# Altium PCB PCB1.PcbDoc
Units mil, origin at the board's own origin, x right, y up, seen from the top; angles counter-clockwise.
Board outline 4740 x 1980 mil, 4 copper layers (Top Layer, GND, Power, Bottom Layer), stack 63.355 mil thick; 55 components, 31 nets, 157 pads, 23 vias.
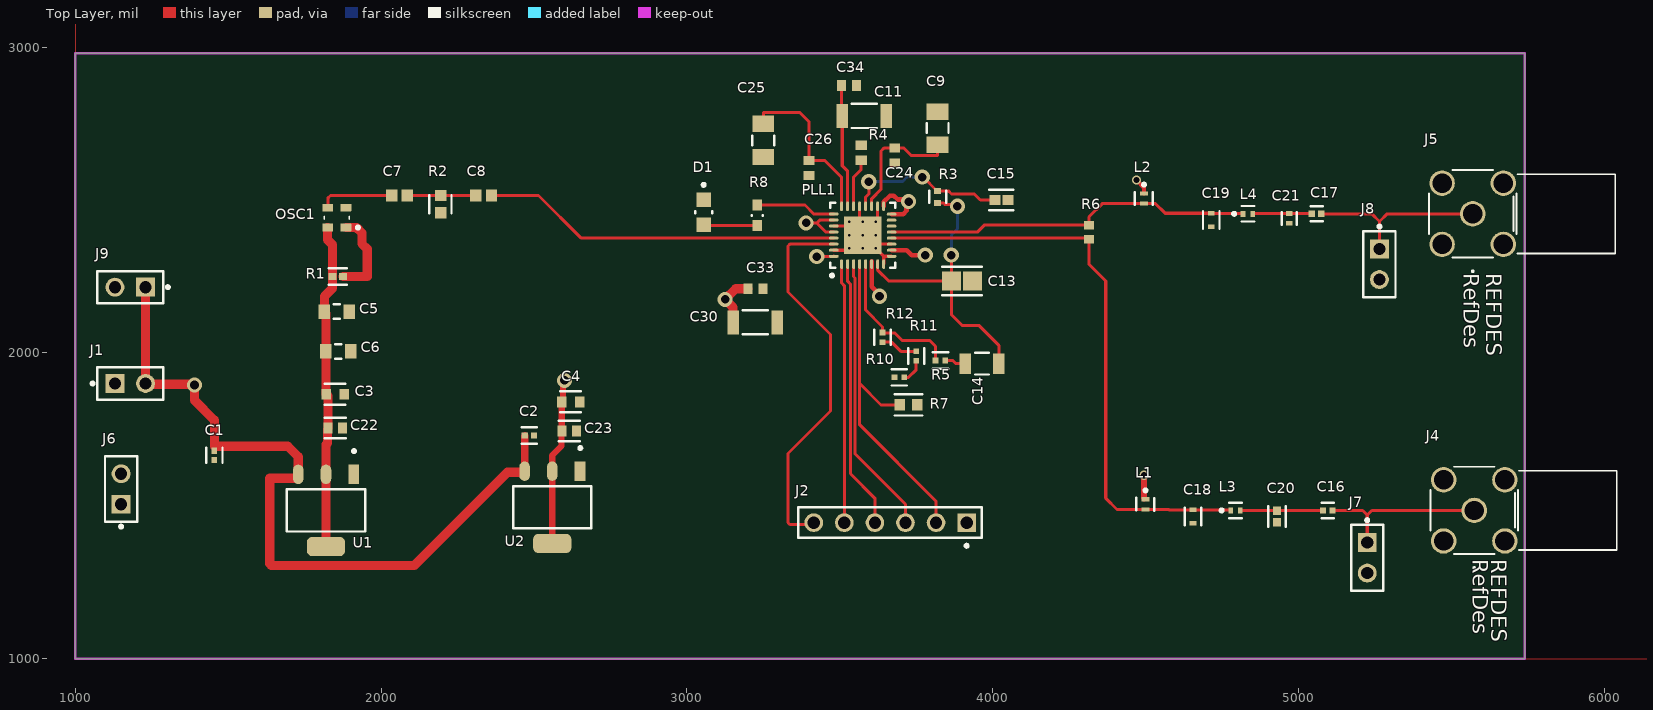
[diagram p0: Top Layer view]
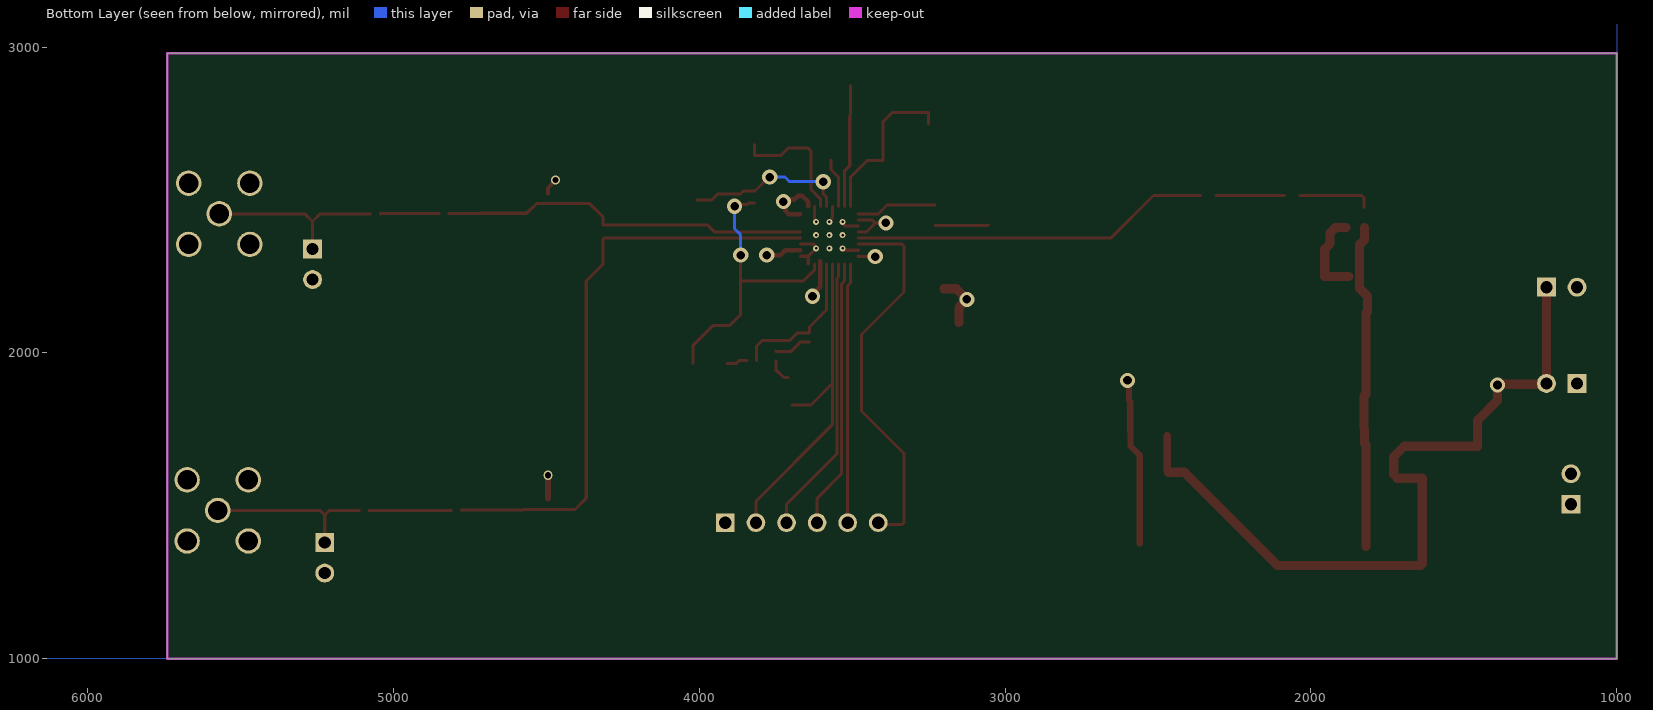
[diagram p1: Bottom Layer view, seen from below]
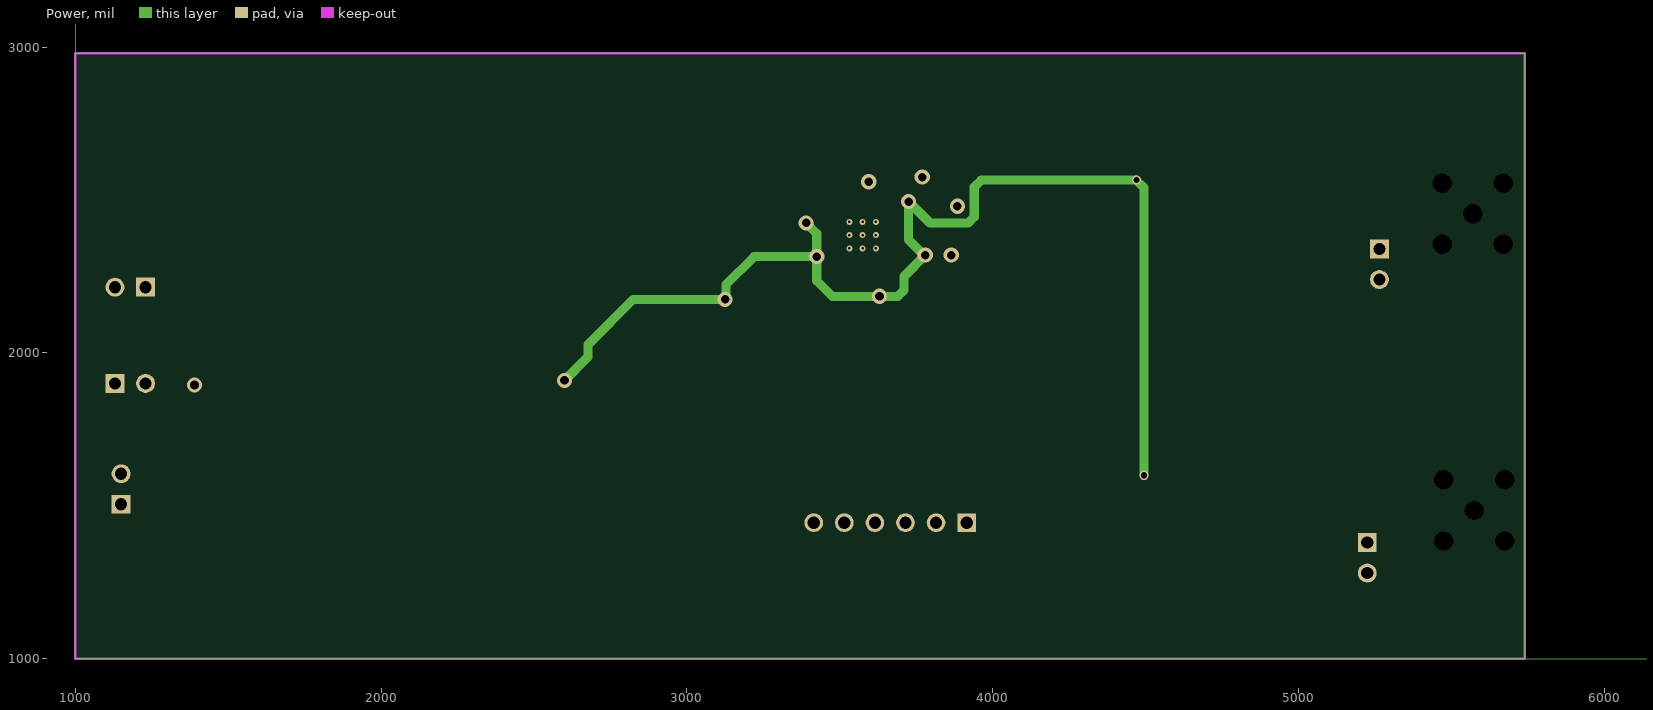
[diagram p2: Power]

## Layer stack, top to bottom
Top Solder: solder mask 1, Solder Resist, Dk 3.6
Top Layer: signal copper 1.378
Dielectric 1: prepreg 7.957, FR-4, Dk 3.61
GND: signal copper 1.378
Core: core 41.929, FR-4, Dk 4.4
Power: signal copper 1.378
Dielectric 2: prepreg 7.957, FR-4, Dk 3.61
Bottom Layer: signal copper 1.378
Bottom Solder: solder mask 1, Solder Resist, Dk 3.6

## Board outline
1000,1000 5740,1000 5740,2980 1000,2980

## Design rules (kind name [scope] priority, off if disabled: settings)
AssemblyTestPointUsage [All] p0: scope1count=1 scope1_0_kind=Board scope1_0_value=Board scope2count=1 scope2_0_kind=Board scope2_0_value=Board commentlength=0
AssemblyTestpoint [All] p0: scope1count=1 scope1_0_kind=Board scope1_0_value=Board scope2count=1 scope2_0_kind=Board scope2_0_value=Board commentlength=0
BoardOutlineClearance [All] p0: scope1count=1 scope1_0_kind=Board scope1_0_value=Board scope2count=1 scope2_0_kind=Board scope2_0_value=Board commentlength=0 gap=15
BoardOutlineClearance [All] p1: gap=15 ignorepadtopadclearanceinfootprint=FALSE
Clearance [All] p0: scope1count=1 scope1_0_kind=Board scope1_0_value=Board scope2count=1 scope2_0_kind=Board scope2_0_value=Board commentlength=0 gap=5
Clearance "Clearance Polygons" [All] p0 off: scope1count=1 scope1_0_kind=Board scope1_0_value=Board scope2count=1 scope2_0_kind=Board scope2_0_value=Board commentlength=48 gap=10 // Protel DXP Scope 1 Expression Was: InPolygon
Clearance "Clearance Polygons" [InPolygon] p1: gap=10 ignorepadtopadclearanceinfootprint=FALSE
Clearance [All] p2: gap=5 ignorepadtopadclearanceinfootprint=FALSE
ComponentClearance [All] p0: scope1count=1 scope1_0_kind=Board scope1_0_value=Board scope2count=1 scope2_0_kind=Board scope2_0_value=Board commentlength=0 gap=1 collisioncheckmode=3
ComponentClearance "HM-TRP & UFL" [All] p0: scope1count=1 scope1_0_kind=Component scope1_0_value=X1 scope2count=1 scope2_0_kind=Component scope2_0_value=U1 commentlength=0 gap=0 collisioncheckmode=3
ComponentClearance "HM-TRP & UFL" [InComponent('X1') vs InComponent('U1')] p1: gap=0 collisioncheckmode=3 verticalgap=0 showdistances=FALSE
ComponentClearance [All] p2: gap=1 collisioncheckmode=3 verticalgap=1 showdistances=FALSE
DiffPairsRouting [All] p0: scope1count=1 scope1_0_kind=Board scope1_0_value=Board scope2count=1 scope2_0_kind=Board scope2_0_value=Board commentlength=0
DiffPairsRouting [All] p1: maxlimit=393.7 minlimit=5 mostfreqgap=8 toplayer_minwidth=5 toplayer_maxwidth=15 toplayer_prefwidth=8 midlayer1_minwidth=5 midlayer1_maxwidth=15 midlayer1_prefwidth=8 midlayer2_minwidth=5 midlayer2_maxwidth=15 midlayer2_prefwidth=8 bottomlayer_minwidth=5 bottomlayer_maxwidth=15 bottomlayer_prefwidth=8 maxuncoupledlength=500
FabricationTestPointUsage [All] p0: scope1count=1 scope1_0_kind=Board scope1_0_value=Board scope2count=1 scope2_0_kind=Board scope2_0_value=Board commentlength=0 valid=0 allowmultiple=FALSE
FabricationTestpoint [All] p0: scope1count=1 scope1_0_kind=Board scope1_0_value=Board scope2count=1 scope2_0_kind=Board scope2_0_value=Board commentlength=0 side=3 testpointundercomponent=TRUE minsize=40 maxsize=100 preferedsize=60 minholesize=0 maxholesize=40 preferedholesize=32 testpointgrid=1
FanoutControl Fanout_Default [All] p0: scope1count=1 scope1_0_kind=Board scope1_0_value=Board scope2count=1 scope2_0_kind=Board scope2_0_value=Board commentlength=30 // Fanout_Default (Default Rule)
FanoutControl Fanout_Small [All] p0 off: scope1count=1 scope1_0_kind=Board scope1_0_value=Board scope2count=1 scope2_0_kind=Board scope2_0_value=Board commentlength=84 // Protel DXP Scope 1 Expression Was: (CompPinCount < 5)   Fanout_Small (Default Rule)
FanoutControl Fanout_SOIC [All] p0 off: scope1count=1 scope1_0_kind=Board scope1_0_value=Board scope2count=1 scope2_0_kind=Board scope2_0_value=Board commentlength=71 // Protel DXP Scope 1 Expression Was: IsSOIC   Fanout_SOIC (Default Rule)
FanoutControl Fanout_LCC [All] p0 off: scope1count=1 scope1_0_kind=Board scope1_0_value=Board scope2count=1 scope2_0_kind=Board scope2_0_value=Board commentlength=69 // Protel DXP Scope 1 Expression Was: IsLCC   Fanout_LCC (Default Rule)
FanoutControl Fanout_BGA [All] p0 off: scope1count=1 scope1_0_kind=Board scope1_0_value=Board scope2count=1 scope2_0_kind=Board scope2_0_value=Board commentlength=69 // Protel DXP Scope 1 Expression Was: IsBGA   Fanout_BGA (Default Rule)
Height [All] p0: scope1count=1 scope1_0_kind=Board scope1_0_value=Board scope2count=1 scope2_0_kind=Board scope2_0_value=Board commentlength=0
HoleSize [All] p0: scope1count=1 scope1_0_kind=Board scope1_0_value=Board scope2count=1 scope2_0_kind=Board scope2_0_value=Board commentlength=0 absolutevalues=TRUE maxlimit=265 minlimit=10 maxpercent=80.000 minpercent=20.000
HoleSize [All] p1: absolutevalues=TRUE maxlimit=265 minlimit=10 maxpercent=80.000 minpercent=20.000
HoleToHoleClearance [All] p0: scope1count=1 scope1_0_kind=Board scope1_0_value=Board scope2count=1 scope2_0_kind=Board scope2_0_value=Board commentlength=0
HoleToHoleClearance [All] p1: gap=10 allowstackedmicrovias=FALSE
LayerPairs [All] p0: scope1count=1 scope1_0_kind=Board scope1_0_value=Board scope2count=1 scope2_0_kind=Board scope2_0_value=Board commentlength=0 enforce=TRUE
MinimumAnnularRing [All] p0: scope1count=1 scope1_0_kind=Board scope1_0_value=Board scope2count=1 scope2_0_kind=Board scope2_0_value=Board commentlength=0 minimumring=4
MinimumAnnularRing [All] p1: minimumring=4
MinimumSolderMaskSliver [All] p0: scope1count=1 scope1_0_kind=Board scope1_0_value=Board scope2count=1 scope2_0_kind=Board scope2_0_value=Board commentlength=0
MinimumSolderMaskSliver [All] p1: minsoldermaskwidth=0
NetAntennae [All] p0: scope1count=1 scope1_0_kind=Board scope1_0_value=Board scope2count=1 scope2_0_kind=Board scope2_0_value=Board commentlength=0
PasteMaskExpansion [All] p0: scope1count=1 scope1_0_kind=Board scope1_0_value=Board scope2count=1 scope2_0_kind=Board scope2_0_value=Board commentlength=0 expansion=0
PlaneClearance [All] p0: scope1count=1 scope1_0_kind=Board scope1_0_value=Board scope2count=1 scope2_0_kind=Board scope2_0_value=Board commentlength=0 clearance=10
PlaneClearance [All] p1: clearance=10
PlaneConnect [All] p0: scope1count=1 scope1_0_kind=Board scope1_0_value=Board scope2count=1 scope2_0_kind=Board scope2_0_value=Board commentlength=0 planeconnectstyle=Relief reliefexpansion=4 reliefentries=4 reliefconductorwidth=6 reliefairgap=6
PlaneConnect [All] p1: planeconnectstyle=Relief reliefexpansion=4 reliefentries=4 reliefconductorwidth=6 reliefairgap=6
PolygonConnect [All] p0: scope1count=1 scope1_0_kind=Board scope1_0_value=Board scope2count=1 scope2_0_kind=Board scope2_0_value=Board commentlength=0 connectstyle=Relief reliefconductorwidth=10 reliefentries=4 polygonreliefangle="90 Angle"
PolygonConnect "Via connect style" [All] p0 off: scope1count=1 scope1_0_kind=Board scope1_0_value=Board scope2count=1 scope2_0_kind=Board scope2_0_value=Board commentlength=44 connectstyle=Direct reliefconductorwidth=10 reliefentries=4 polygonreliefangle="90 Angle" // Protel DXP Scope 1 Expression Was: isVia
PolygonConnect "Via connect style" [isVia] p1: connectstyle=Direct reliefconductorwidth=10 reliefentries=4 polygonreliefangle="90 Angle" airgapwidth=10
PolygonConnect [All] p2: connectstyle=Relief reliefconductorwidth=10 reliefentries=4 polygonreliefangle="90 Angle" airgapwidth=6
RoutingCorners [All] p0: scope1count=1 scope1_0_kind=Board scope1_0_value=Board scope2count=1 scope2_0_kind=Board scope2_0_value=Board commentlength=0 cornerstyle=45-Degree minsetback=49.21 maxsetback=49.21
RoutingCorners [All] p1: cornerstyle=45-Degree minsetback=49.21 maxsetback=49.21
RoutingLayers [All] p0: scope1count=1 scope1_0_kind=Board scope1_0_value=Board scope2count=1 scope2_0_kind=Board scope2_0_value=Board commentlength=0 top layer=Automatic mid layer 1=Automatic mid layer 2=Automatic bottom layer=Automatic
RoutingPriority [All] p0: scope1count=1 scope1_0_kind=Board scope1_0_value=Board scope2count=1 scope2_0_kind=Board scope2_0_value=Board commentlength=0
RoutingTopology [All] p0: scope1count=1 scope1_0_kind=Board scope1_0_value=Board scope2count=1 scope2_0_kind=Board scope2_0_value=Board commentlength=0 topology=Shortest
RoutingVias [All] p0: scope1count=1 scope1_0_kind=Board scope1_0_value=Board scope2count=1 scope2_0_kind=Board scope2_0_value=Board commentlength=0 holewidth=12 width=22 viastyle="Through Hole" minholewidth=10 minwidth=18 maxholewidth=100 maxwidth=114
RoutingVias [All] p1: holewidth=12 width=22 viastyle="Through Hole" minholewidth=10 minwidth=18 maxholewidth=100 maxwidth=114
ShortCircuit [All] p0: scope1count=1 scope1_0_kind=Board scope1_0_value=Board scope2count=1 scope2_0_kind=Board scope2_0_value=Board commentlength=0 allowed=FALSE
SilkToBoardRegionClearance [All] p0: scope1count=1 scope1_0_kind=Board scope1_0_value=Board scope2count=1 scope2_0_kind=Board scope2_0_value=Board commentlength=0
SilkToSilkClearance [All] p0: scope1count=1 scope1_0_kind=Board scope1_0_value=Board scope2count=1 scope2_0_kind=Board scope2_0_value=Board commentlength=0
SilkToSilkClearance [All] p1: silktosilkclearance=0
SilkToSolderMaskClearance [All] p0 off: scope1count=1 scope1_0_kind=Board scope1_0_value=Board scope2count=1 scope2_0_kind=Board scope2_0_value=Board commentlength=44 // Protel DXP Scope 1 Expression Was: IsPad
SilkToSolderMaskClearance [IsPad] p1: minsilkscreentomaskgap=5 clearancetoexposedcopper=TRUE
SolderMaskExpansion [All] p0: scope1count=1 scope1_0_kind=Board scope1_0_value=Board scope2count=1 scope2_0_kind=Board scope2_0_value=Board commentlength=0 expansion=2.5
SolderMaskExpansion [All] p1: expansion=2.5 istentingtop=FALSE
SupplyNets "Schematic Supply Nets" [All] p0: scope1count=1 scope1_0_kind=Net scope1_0_value=GND scope2count=1 scope2_0_kind=Board scope2_0_value=Board commentlength=0 voltage=0.000
SupplyNets "Schematic Supply Nets" [InNet('GND')] p1: voltage=0.000
UnRoutedNet [All] p0: scope1count=1 scope1_0_kind=Board scope1_0_value=Board scope2count=1 scope2_0_kind=Board scope2_0_value=Board commentlength=0
UnpouredPolygon [All] p0: scope1count=1 scope1_0_kind=Board scope1_0_value=Board scope2count=1 scope2_0_kind=Board scope2_0_value=Board commentlength=0
Width [All] p0: scope1count=1 scope1_0_kind=Board scope1_0_value=Board scope2count=1 scope2_0_kind=Board scope2_0_value=Board commentlength=0 maxlimit=400 minlimit=6 preferedwidth=8
Width 3V3 [All] p0: scope1count=1 scope1_0_kind=NetClass scope1_0_value=3V3 scope2count=1 scope2_0_kind=Board scope2_0_value=Board commentlength=0 maxlimit=30 minlimit=10 preferedwidth=20
Width Power [All] p0: scope1count=1 scope1_0_kind=NetClass scope1_0_value=Power scope2count=1 scope2_0_kind=Board scope2_0_value=Board commentlength=0 maxlimit=40 minlimit=20 preferedwidth=30
Width GND [All] p0: scope1count=1 scope1_0_kind=Net scope1_0_value=GND scope2count=1 scope2_0_kind=Board scope2_0_value=Board commentlength=0 maxlimit=30 minlimit=10 preferedwidth=20
Width GND [InNet('GND')] p1: maxlimit=30 minlimit=10 preferedwidth=20
Width Power [InNetClass('Power')] p2: maxlimit=40 minlimit=20 preferedwidth=30
Width 3V3 [InNetClass('3V3')] p3: maxlimit=30 minlimit=10 preferedwidth=20
Width [All] p4: maxlimit=400 minlimit=6 preferedwidth=8
20 further rules are at their usual default settings.

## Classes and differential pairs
component class "Power Schematic": C1 C2 C3 C4 C22 C23 C30 C33 U1 U2
component class FreqSynth: C5 C6 C7 C8 C9 C11 C13 C14 C15 C16 C17 C18 C19 C20 C21 C24 C25 C26 C34 D1 J1 J2 J4 J5 J6 J7 J8 J9 L1 L2 L3 L4 OSC1 PLL1 R1 R2 R3 R4 R5 R6 R7 R8 R10 R11 R12

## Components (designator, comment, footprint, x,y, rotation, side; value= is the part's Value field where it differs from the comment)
C1 "1uF" FP-GRT155-0_05-IPC_C 1455,1665 r270 top
C2 "1uF" FP-GRT155-0_05-IPC_C 2485,1730 r0 top
C3 "4.7uF" FP-CC0603-DC-MFG 1850,1865 r0 top
C4 "4.7uF" FP-CC0603-DC-MFG 2620,1840 r0 top
C5 "1nF" FP-CGA3E-0_3-0_1-IPC_A 1855,2135 r0 top
C6 "1nF" FP-CGA3E-0_3-0_1-IPC_A 1860,2005 r0 top
C7 "1nF" CAPC1608X95X40NL15T15 2060.59,2515 r0 top
C8 "1nF" CAPC1608X95X40NL15T15 2335.59,2515 r0 top
C9 "100nF" FP-GRM31C-0_2-e0_3_0_8-IPC_B 3820,2735 r90 top
C11 "100nF" FP-CGA5L-0_3-0_1-IPC_A 3580,2775 r0 top
C13 "2.7nF" FP-C2012-125-0_2-IPC_A 3900,2235 r0 top
C14 "39nF" FP-C1206C-EB-MFG 3965,1965 r180 top
C15 "1.2nF" FP-C1608-080-0_1-IPC_C 4028.72,2500 r0 top
C16 "1nF" FP-C0402C102K4RAC7411-MFG 5095.75,1485 r0 top
C17 "1nF" FP-C0402C102K4RAC7411-MFG 5059.25,2455 r0 top
C18 "2.2pF" FP-CGA2B-IPC_B 4655,1465 r270 top
C19 "2.2pF" FP-CGA2B-IPC_B 4715,2435 r270 top
C20 "1.5pF" FP-GCM155-0_05-IPC_A 4930,1465 r270 top
C21 "1.5pF" FP-CGA2B-MFG 4970,2440 r270 top
C22 "4.7pF" FP-C0603C-CF-MFG 1850,1755 r0 top
C23 "4.7pF" FP-C0603C-CF-MFG 2615,1745 r0 top
C24 "10pF" CAPC1608X92X38LL15T08 3680,2645 r90 top
C25 "100nF" FP-GRM31C-0_2-e0_3_0_8-IPC_B 3250,2695 r270 top
C26 "10pF" CAPC1608X92X38LL15T08 3400,2605 r90 top
C30 "100nF" FP-CGA5L-0_3-0_1-IPC_A 3223.15,2100 r0 top
C33 "10pF" CAPC1608X92X38LL15T08 3225,2210 r180 top
C34 "10pF" CAPC1608X92X38LL15T08 3530.39,2875 r180 top
D1 "GREEN LED" FP-LG_R971-MFG 3055,2460 r270 top
J1 "TSW-102-07-L-S" FP-TSW-102-07-L-S-MFG 1180,1900 r0 top
J2 "TSW-106-07-S-S" SMTC-TSW-106-07-S-S_V 3665,1445 r180 top
J4 "SMA-J-P-H-RA-TH1" CONN_SMA-J-P-H-RA-TH1_SAI 5575,1485 r270 top
J5 "SMA-J-P-H-RA-TH1" CONN_SMA-J-P-H-RA-TH1_SAI 5570,2455 r270 top
J6 "TSW-102-07-L-S" FP-TSW-102-07-L-S-MFG 1150,1555 r90 top
J7 "TSW-102-07-L-S" FP-TSW-102-07-L-S-MFG 5225,1330 r270 top
J8 "TSW-102-07-L-S" FP-TSW-102-07-L-S-MFG 5265,2290 r270 top
J9 "TSW-102-07-L-S" FP-TSW-102-07-L-S-MFG 1180,2215 r180 top
L1 "7.5nH" FP-LQG15WH_02-MFG 4500,1505 r270 top
L2 "7.5nH" FP-LQG15WH_02-MFG 4495,2505 r270 top
L3 "3.6nH" FP-LQG15HH_02-MFG 4794.25,1485 r0 top
L4 "3.6nH" FP-LQG15HH_02-MFG 4835,2455 r0 top
OSC1 "LMK6CE10000DDLFT" DLF0004A_MFG 1855.47,2442.52 r180 top
PLL1 "ADF4350BCPZ-RL7" ADI-CP-32-2_L 3575,2385 r90 top
R1 "10k" FP-CRG0402-IPC_B 1858.22,2250 r0 top
R2 "51" FP-CRCW0603-e3-IPC_B 2195,2486.83 r270 top
R3 "680" FP-RT0402-MFG 3820,2510 r90 top
R4 "4.7k" RESC1609X50X30NL10T20 3570,2655 r90 top
R5 "360" FP-CRCW0402-e3-IPC_C 3829.17,1975 r180 top
R6 "100" RESC1609X50X30LL10T20 4315,2395 r270 top
R7 "10k" FP-MCT0603-IPC_B 3725,1830 r0 top
R8 "100" FP-SR0603-MFG 3230,2450 r270 top
R10 "360" FP-CRCW0402-e3-IPC_C 3695,1920 r180 top
R11 "360" FP-CRCW0402-e3-IPC_C 3750,1990 r270 top
R12 "360" FP-CRCW0402-e3-IPC_C 3640,2050.83 r270 top
U1 "LDL1117S33R" FP-SOT223-0046067-IPC_C 1820,1485 r270 top
U2 "LDL1117S33R" FP-SOT223-0046067-IPC_C 2560,1495 r270 top

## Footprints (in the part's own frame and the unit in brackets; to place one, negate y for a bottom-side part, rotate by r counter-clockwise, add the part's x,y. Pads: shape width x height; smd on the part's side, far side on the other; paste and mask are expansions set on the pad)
ADI-CP-32-2_L [mm] "QFN, 32-Leads, Body 5x5mm, Pitch 0.5mm, Thermal Pad 3.1x3.1mm, IPC High Density"
  oval 0.8x0.25 smd: 1(-2.4,1.75) 2(-2.4,1.25) 3(-2.4,0.75) 4(-2.4,0.25) 5(-2.4,-0.25) 6(-2.4,-0.75) 7(-2.4,-1.25) 8(-2.4,-1.75) 17(2.4,-1.75) 18(2.4,-1.25) 19(2.4,-0.75) 20(2.4,-0.25) 21(2.4,0.25) 22(2.4,0.75) 23(2.4,1.25) 24(2.4,1.75)
  oval 0.25x0.8 smd: 9(-1.75,-2.4) 10(-1.25,-2.4) 11(-0.75,-2.4) 12(-0.25,-2.4) 13(0.25,-2.4) 14(0.75,-2.4) 15(1.25,-2.4) 16(1.75,-2.4) 25(1.75,2.4) 26(1.25,2.4) 27(0.75,2.4) 28(0.25,2.4) 29(-0.25,2.4) 30(-0.75,2.4) 31(-1.25,2.4) 32(-1.75,2.4)
  rect 3.1x3.1 smd: 33(0,0)
  silkscreen extent -3.47,-2.7 2.7,2.7
CAPC1608X92X38LL15T08 [mm] "Chip Capacitor, 2-Leads, Body 1.60x0.80mm, IPC High Density"
  rect 0.75x0.9 smd: 1(-0.625,0) 2(0.625,0)
CAPC1608X95X40NL15T15 [mm] "Chip Capacitor, 2-Leads, Body 1.60x0.80mm, IPC Medium Density"
  rect 0.95x1 smd: 1(-0.65,0) 2(0.65,0)
CONN_SMA-J-P-H-RA-TH1_SAI [mil]
  round 83 / inner round 60 / far side round 83 hole 63 paste+0 mask+0: 1(0,0) 2(-100,100) 3(-100,-100) 4(100,-100) 5(100,100)
  silkscreen extent -143,-143 191,466
DLF0004A_MFG [mm] "Recommended Land Pattern"
  rrect15% 0.9x0.65 smd: 1(-0.75,0.825) 2(-0.75,-0.825) 3(0.75,-0.825) 4(0.75,0.825)
  silkscreen extent -1.88,-0.13 1.05,0.95
FP-C0402C102K4RAC7411-MFG [mm]
  rect 0.52x0.52 smd paste+0 mask+0: 1(-0.4,0) 2(0.4,0)
  silkscreen extent -0.5,-0.64 0.5,0.64
FP-C0603C-CF-MFG [mm]
  rect 0.75x0.9 smd paste+0 mask+0: 1(-0.6,0) 2(0.6,0)
  silkscreen extent -0.87,-0.85 0.88,0.85
FP-C1206C-EB-MFG [mm]
  rect 0.95x1.7 smd paste+0 mask+0: 1(-1.4,0) 2(1.4,0)
  silkscreen extent -0.55,-0.9 0.55,0.9
FP-C1608-080-0_1-IPC_C [mil]
  rect 36.66x31.97 smd paste+0 mask+0: 1(-21.28,0) 2(21.28,0)
  silkscreen extent -40,-33 40,33
FP-C2012-125-0_2-IPC_A [mil]
  rect 62.13x61.27 smd paste+0 mask+0: 1(-34.02,0) 2(34.02,0)
  silkscreen extent -65,-46 65,46
FP-CC0603-DC-MFG [mm]
  rect 0.8x0.9 smd paste+0 mask+0: 1(-0.75,0) 2(0.75,0)
  silkscreen extent -0.85,-0.87 0.85,0.87
FP-CGA2B-IPC_B [mm]
  rect 0.372x0.572 smd paste+0 mask+0: 1(-0.55,0) 2(0.55,0)
  silkscreen extent -0.74,-0.69 0.74,0.69
FP-CGA2B-MFG [mm]
  rect 0.4x0.5 smd paste+0 mask+0: 1(-0.4,0) 2(0.4,0)
  silkscreen extent -0.53,-0.63 0.53,0.63
FP-CGA3E-0_3-0_1-IPC_A [mm]
  rect 0.956x1.206 smd paste+0 mask+0: 1(-1.025,0) 2(1.025,0)
  silkscreen extent -0.25,-0.6 0.25,0.6
FP-CGA5L-0_3-0_1-IPC_A [mm]
  rect 0.956x2.006 smd paste+0 mask+0: 1(-1.825,0) 2(1.825,0)
  silkscreen extent -1.05,-1 1.05,1
FP-CRCW0402-e3-IPC_C [mil]
  rect 18.43x18.6 smd paste+0 mask+0: 1(-15.83,0) 2(15.83,0)
  silkscreen extent -25,-27 25,27
FP-CRCW0603-e3-IPC_B [mil]
  rect 36.81x37.88 smd paste+0 mask+0: 1(-28.17,0) 2(28.17,0)
  silkscreen extent -30,-37 30,35
FP-CRG0402-IPC_B [mil]
  rect 25.97x22.54 smd paste+0 mask+0: 1(-16.78,0) 2(16.78,0)
  silkscreen extent -30,-27 30,27
FP-GCM155-0_05-IPC_A [mil]
  rect 28.16x26.48 smd paste+0 mask+0: 1(-18.84,0) 2(18.84,0)
  silkscreen extent -33,-29 33,29
FP-GRM31C-0_2-e0_3_0_8-IPC_B [mil]
  rect 53.33x71.11 smd paste+0 mask+0: 1(-54.16,0) 2(54.16,0)
  silkscreen extent -16,-36 16,36
FP-GRT155-0_05-IPC_C [mil]
  rect 20.29x18.6 smd paste+0 mask+0: 1(-14.9,0) 2(14.9,0)
  silkscreen extent -25,-27 25,27
FP-LG_R971-MFG [mm]
  rect 1.2x1.2 smd paste+0 mask+0: 1(-1.05,0) 2(1.05,0)
  silkscreen extent -2.4,-0.7 0.08,0.7
FP-LQG15HH_02-MFG [mm]
  rect 0.4x0.5 smd paste+0 mask+0: 1(-0.4,0) 2(0.4,0)
  silkscreen extent -1.27,-0.64 0.53,0.65
FP-LQG15WH_02-MFG [mm]
  rect 0.35x0.65 smd paste+0 mask+0: 1(-0.425,0) 2(0.425,0)
  silkscreen extent -1.27,-0.78 0.53,0.72
FP-MCT0603-IPC_B [mil]
  rect 34x37.88 smd paste+0 mask+0: 1(-28.72,0) 2(28.72,0)
  silkscreen extent -46,-35 46,35
FP-RT0402-MFG [mm]
  rect 0.5x0.6 smd paste+0 mask+0: 1(-0.5,0) 2(0.5,0)
  silkscreen extent -0.5,-0.71 0.5,0.7
FP-SOT223-0046067-IPC_C [mm]
  rect 1.604x0.88 smd paste+0 mask+0: 1(-3,2.3)
  rrect100% 1.604x0.88 smd paste+0 mask+0: 2(-3,0) 3(-3,-2.3)
  rrect55% 1.604x3.18 smd paste+0 mask+0: 4(3,0)
  silkscreen extent -5.05,-3.25 1.75,3.25
FP-SR0603-MFG [mm]
  rect 0.9x0.8 smd paste+0 mask+0: 1(-0.85,0) 2(0.85,0)
  silkscreen extent -0.03,-0.45 0.03,0.45
FP-TSW-102-07-L-S-MFG [mm]
  rect 1.57x1.57 hole 1.02 paste+0 mask+0: 1(-1.27,0)
  round 1.57 hole 1.02 paste+0 mask+0: 2(1.27,0)
  silkscreen extent -3.25,-1.34 2.73,1.34
RESC1609X50X30LL10T20 [mm] "Chip Resistor, 2-Leads, Body 1.55x0.85mm, IPC High Density"
  rect 0.7x0.85 smd: 1(-0.575,0) 2(0.575,0)
RESC1609X50X30NL10T20 [mm] "Chip Resistor, 2-Leads, Body 1.55x0.85mm, IPC Medium Density"
  rect 0.8x0.95 smd: 1(-0.625,0) 2(0.625,0)
SMTC-TSW-106-07-S-S_V [mm] "Header, 6-Leads, Body 15.24x2.54mm, Pitch 2.54mm"
  rect 1.55x1.55 hole 1.02: 1(-6.35,0)
  round 1.55 hole 1.02: 2(-3.81,0) 3(-1.27,0) 4(1.27,0) 5(3.81,0) 6(6.35,0)
  silkscreen extent -7.62,-1.27 7.62,2.04

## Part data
C1 C2: library part CMP-06035-034802-1, "Multi-Layer Ceramic Capacitor 1uF 6.3V X7R ±10% 0402 Paper T/R"
C3 C4: library part CMP-03422-001038-2, "CAP CER 4.7UF 6.3V X7R 0603"
C5 C6: library part CMP-08246-001196-1, "Cap Ceramic 1nF 250V C0G 5% Pad SMD 0603 +125°C Automotive T/R"
C7 C8: library part CMP-2006-01663-1
C9 C25: library part CMP-06035-003994-1, "Chip Multilayer Ceramic Capacitors for General Purpose, 1206, 0.10uF, C0G, 30ppm/°C, 5%, 50V"
C11 C30: library part CMP-08246-001706-1, "Cap Ceramic 100nF 100V C0G 5% Pad SMD 1206 +125°C Automotive T/R"
C13: library part CMP-08246-005643-1, "Multilayer Ceramic Capacitors 2.7nF ±5% 250V C0G SMD 0805"
C14: library part CMP-03020-008489-1, "C1206 39,000 pF C0G 5.00% 50 V"
C15: library part CMP-08246-006367-1, "Multilayer Ceramic Capacitors 1.2nF ±5% 100V C0G SMD 0603"
C16 C17: library part CMP-03020-021251-2, "CAP CER 1000PF 16V X7R 0402"
C18 C19: library part CMP-08246-000350-1, "Cap Ceramic 2.2pF 50V C0G 0.25pF Pad SMD 0402 +125°C Automotive T/R"
C20: library part CMP-06035-012333-1, "Ceramic Capacitor for Automotive 1.5pF ±5% 50VDC C0G 0402 Paper T/R"
C21: library part CMP-08246-001768-1, "Cap Ceramic 1.5pF 50V C0G 0.25pF Pad SMD 0402 +125°C Automotive T/R"
C22 C23: library part CMP-03020-020744-1, "C0603 4.7 pF C0G 30ppm/°C 0.25 pF 50 V"
C24 C26 C33 C34: library part CMP-2006-01151-1
D1: library part CMP-62016-000039-1, "LED GREEN DIFFUSED 0805 SMD"
J1 J6 J7 J8 J9: library part CMP-02766-001428-1, "CONN HEADER VERT 2POS 2.54MM"
J2: library part CMP-1681-00007-2, "Male Header, Pitch 2.54 mm, 1 x 6 Position, Height 8.38 mm, Tail Length 2.54 mm, -55 to 125 degC, RoHS, Bulk"
J4 J5: library part CMP-009-000000-1, "Description"
L1 L2: library part CMP-06042-014192-1, "Multilayer type Inductor for Automotive 7.5nH ±3% 0.16O 600mA 0402"
L3 L4: library part CMP-06042-009995-1, "Multilayer type RF Inductor 3.6nH ±0.2nH 0.14O 750mA 0402"
OSC1: library part CMP-00370-145325626-1, "IC 100 MHz LVCMOS Oscillator 1.8V Enable/Disable 4-VDFN"
PLL1: library part CMP-0287-00013-1, "Wideband Synthesizer with Integrated VCO, CP-32-2, Pb-Free, 1500 Reel"
R1: library part CMP-03211-011410-1, "RES SMD 10K OHM 1% 1/16W 0402"
R2: library part CMP-2000-03447-2, "RES Thick Film, 51O, 5%, 0.1W, 200ppm/°C, 0603"
R3: library part CMP-2002-02756-2, "RES SMD 680 OHM 0.1% 1/16W 0402"
R4: library part CMP-2000-03412-1
R5 R10 R11 R12: library part CMP-2002-08546-2, "RES Thick Film, 360O, 1%, 0.063W, 100ppm/°C, 0402"
R6: library part CMP-2000-03826-1
R7: library part CMP-02407-001090-1, "RES SMD 100 OHM 1% 1/8W 0603"
R8: library part CMP-03412-002710-1, "RES SMD 0603 1/4W 1% 100 OHM"
U1 U2: library part CMP-12153-000006-1, "IC REG LINEAR 3.3V 1.2A SOT223"

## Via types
v1: diameter 50, hole 28, Top Layer to Bottom Layer, 12 vias
v2: diameter 19.68, hole 7.87, Top Layer to Bottom Layer, 9 vias
v3: diameter 30, hole 20, Top Layer to Bottom Layer, 2 vias

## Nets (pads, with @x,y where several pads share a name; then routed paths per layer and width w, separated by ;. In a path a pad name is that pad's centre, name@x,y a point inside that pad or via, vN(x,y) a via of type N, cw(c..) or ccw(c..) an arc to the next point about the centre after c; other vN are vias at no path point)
GND: C1.2 C2.2 C3.2 C4.2 C5.2 C6.2 C9.2 C11.2 C13.2 C15.2 C18.2 C19.2 C20.2 C21.2 C22.2 C23.2 C24.1 C25.2 C26.1 C30.2 C33.1 C34.1 D1.1 J1.1 J2.1 J4.2 J4.3 J4.4 J4.5 J5.2 J5.3 J5.4 J5.5 J6.1 J6.2 J7.2 J8.2 J9.2 OSC1.2 PLL1.8 PLL1.9 PLL1.11 PLL1.18 PLL1.21 PLL1.27 PLL1.31 PLL1.33 R2.2 R4.2 R7.2 R10.2 U1.1 U2.1 | length 371.2
  Top Layer w10: PLL1.31 3525.79,2335.79 v2(3531.69,2341.69) ; PLL1.27 3523.98,2414.53 3531.69,2422.24 v2(3531.69,2428.31) ; PLL1.21 3565.16,2444.12 3566.54,2442.74 3566.54,2436.02 3574.25,2428.31 v2(3575,2428.31) ; v2(3618.31,2428.31) 3624.21,2434.21 PLL1.18 ; PLL1.8 3643.9,2316.1 ; PLL1.9 3643.9,2316.1 ; PLL1.11 3626.02,2355.47 3618.31,2347.76 v2(3618.31,2341.69) 3643.9,2316.1
  other v2: 3575,2341.69 3531.69,2385 3575,2385 3618.31,2385
NetC1_1: C1.1 C2.1 J1.2 J9.1 U1.3 U2.3 | length 2510.1
  Top Layer w10: J1.2 J1.2@1232.5,1897.5 ; v1@1387.5,1897.5 v1(1390,1895) ; U1.3@1718.07,1590 1729.45,1601.38 U1.3 ; U2.3@2466.34,1610 U2.3 U2.3@2469.77,1613.43 ; C2.1@2469.77,1729.68 C2.1
  Top Layer w25: U2.3@2469.77,1613.43 C2.1@2469.77,1729.68
  Top Layer w30: J1.2 J9.1 ; J1.2@1232.5,1897.5 v1@1387.5,1897.5 ; v1(1390,1895) 1390,1845 1455,1780 1455,1695 1695,1695 1729.45,1660.55 U1.3 ; U1.3@1718.07,1590 1635.86,1590 1635.86,1310.86 1641.72,1305 2108.74,1305 2413.74,1610 U2.3@2466.34,1610
NetC3_1: C3.1 C5.1 C6.1 C22.1 OSC1.4 R1.1 U1.2 U1.4 | length 1063.4
  Top Layer w10: C5.1@1815,2135.35 C5.1 C5.1@1819.65,2130 ; OSC1.4@1825,2409.09 OSC1.4
  Top Layer w30: C5.1@1815,2135.35 1815,2185 1841.44,2211.44 R1.1 1841.44,2353.56 1825,2370 OSC1.4@1825,2409.09 ; C5.1@1819.65,2130 C6.1 1819.65,1865.83 1826.38,1859.09 C22.1 ; U1.4 U1.2 1820,1700 1825,1705 C22.1@1825,1750
NetC4_1: C4.1 C23.1 C30.1 C33.2 L1.1 L2.1 PLL1.6 PLL1.10 PLL1.16 PLL1.17 PLL1.26 PLL1.28 PLL1.32 U2.2 U2.4 | length 5295.9
  Top Layer w10: C23.1@2590,1743.62 C23.1 ; v1(3390,2425) 3425,2425 ; v1(3425,2315) 3465,2315 3466.02,2316.02 3480.43,2316.02 PLL1.32 ; PLL1.28 3480.43,2394.92 3455.08,2394.92 3425,2425 ; PLL1.26 3434.21,2434.21 3425,2425 ; v1(3630,2185) v1@3630,2190.62 ; L1.1@4495,1524.62 4497.89,1521.73 L1.1
  Top Layer w13: v3(4470,2565) 4495,2540 L2.1
  Top Layer w15: PLL1.6@3604.53,2300 PLL1.6 3604.53,2216.1 v1@3630,2190.62 ; PLL1.17 3643.9,2493.9 3664.39,2514.39 3676.81,2514.39 3689.5,2501.7 3718.3,2501.7 v1(3725,2495) 3718.3,2488.3 3718.3,2464.46 3707.74,2453.9 PLL1.16 ; PLL1.10 3719.21,2335.79 3735,2320 v1(3780,2320)
  Top Layer w20: U2.4 U2.2 2560,1665 2590,1695 C23.1@2590,1743.62 ; C23.1 2590.93,1745.45 2590.93,1839.55 C4.1 2595.24,1844.76 2595.24,1905.24 v1(2600,1910) ; L1.1@4495,1524.62 v3(4495,1600)
  Top Layer w30: C30.1 3151.3,2148.7 v1(3125,2175) 3160,2210 C33.2
  Power w8: v1@3775,2320 v1(3780,2320)
  Power w30: v1(2600,1910) 2676.91,1986.91 2676.91,2026.91 2825,2175 v1@3130.41,2175 ; v1(3125,2175) 3127.75,2177.75 3127.75,2222.75 3220,2315 v1(3425,2315) ; v1(3390,2425) 3425,2390 v1(3425,2315) ; v1@3775,2320 3725,2370 v1(3725,2495) 3795,2425 3920,2425 3940,2445 3940,2542.43 3962.57,2565 v3(4470,2565) 4495,2540 v3(4495,1600) ; v1(3780,2320) 3710,2250 3710,2205 3690,2185 v1(3630,2185) 3475.86,2185 3425,2235.86 v1(3425,2315)
NetC7_1: C7.1 OSC1.3 | length 243.8
  Top Layer w10: OSC1.3 1825.94,2505.94 1835,2515 C7.1
NetC7_2: C7.2 C8.1 R2.1 | length 223.8
  Top Layer w10: C7.2 R2.1 C8.1
NetC8_2: C8.2 PLL1.29 | length 1177.3
  Top Layer w10: C8.2 2515,2515 2654.84,2375.16 PLL1.29
NetC9_1: C9.1 C24.2 PLL1.19 | length 427.2
  Top Layer w8: 3818.46,2645 3820,2646.54
  Top Layer w10: PLL1.19 3604.53,2504.53 3635,2535 3635,2660 3644.41,2669.41 3679.8,2669.41 C24.2 3710.39,2669.61 3735,2645 3818.46,2645 ; 3820,2646.54 C9.1
NetC11_1: C11.1 C34.2 PLL1.23 | length 403.8
  Top Layer w10: C34.2 3505.79,2777.36 C11.1 3508.15,2611.85 3525.79,2594.21 PLL1.23
NetC13_1: C13.1 C14.1 PLL1.7 R3.1 | length 965.3
  Top Layer w10: PLL1.7 3624.21,2270.79 3660,2235 C13.1 ; R3.1 3820.32,2490 3840,2490 3845,2485 3880,2485 v1(3885,2480) ; v1(3865,2320) 3865,2235.98 C13.1 ; C14.1 4020.12,2024.88 3955,2090 3900,2090 3865.98,2124.02 C13.1
  Bottom Layer w10: v1(3865,2320) 3865,2386.17 3885,2406.17 v1(3885,2480)
NetC14_2: C14.2 R5.1 | length 69
  Top Layer w10: R5.1 3870,1975 3880,1965 C14.2
NetC15_1: C15.1 PLL1.20 R3.2 | length 534.7
  Top Layer w10: PLL1.20 3584.84,2509.84 3595,2520 v1(3595,2560) ; v1(3770,2575) 3772.72,2575 3818.03,2529.68 R3.2 3820.32,2530 3855,2530 3865.32,2519.68 3940.32,2519.68 3960,2500 C15.1
  Bottom Layer w10: v1(3595,2560) 3705,2560 3720,2575 v1(3770,2575)
NetC16_1: C16.1 C20.1 L3.2 | length 271
  Top Layer w10: L3.2 4810.58,1484.42 4929.42,1484.42 C20.1 4930.58,1484.42 5079.42,1484.42 C16.1
NetC16_2: C16.2 J4.1 J7.1 | length 565.9
  Top Layer w10: C16.2 5210,1485 5225,1470 ; J7.1 5225,1470 ; J4.1 5240,1485 5225,1470
NetC17_1: C17.1 C21.1 L4.2 | length 192.5
  Top Layer w10: L4.2 4851.12,2455.37 4969.63,2455.37 C21.1 4970.37,2455.37 5042.22,2455.37 C17.1@5042.59,2455
NetC17_2: C17.2 J5.1 J8.1 | length 605.7
  Top Layer w10: C17.2 5240,2455 5265,2430 ; J8.1 5265,2430 ; J5.1 5290,2455 5265,2430
NetC18_1: C18.1 L1.2 L3.1 PLL1.12 R6.2 | length 1942.6
  Top Layer w10: PLL1.12 4312.2,2375.16 R6.2 4315,2290 4370,2235 4370,1525 4406.73,1488.27 L1.2 4576.73,1488.27 4579.17,1485.83 4654.17,1485.83 C18.1 4655.83,1485.83 4777.68,1485.83 L3.1
NetC19_1: C19.1 L2.2 L4.1 PLL1.13 R6.1 | length 1218.3
  Top Layer w10: PLL1.13 3949.84,2394.84 3972.64,2417.64 R6.1 4315,2445 4358.27,2488.27 L2.2 4532.57,2488.27 4564.18,2456.65 C19.1 4715.83,2455.83 4818.43,2455.83 L4.1
NetC25_1: C25.1 C26.2 PLL1.24 | length 549.4
  Top Layer w10: C25.1 3250,2786.54 3368.46,2786.54 3400,2755 C26.2 3450.39,2629.61 3506.1,2573.9 PLL1.24
NetD1_2: D1.2 R8.2 | length 175.9
  Top Layer w10: D1.2 3057.13,2416.54 R8.2
NetJ2_2: J2.2 PLL1.4 R7.1 | length 1109.1
  Top Layer w10: PLL1.4 3565.16,1899.92 ; R7.1 3635.08,1830 3565.16,1899.92 ; J2.2 3815,1515 3565.16,1764.84 3565.16,1899.92
NetJ2_3: J2.3 PLL1.3 | length 916.1
  Top Layer w10: PLL1.3 3545.47,2250.47 3545,2250 3550,2245 3550,1670 3715,1505 J2.3
NetJ2_4: J2.4 PLL1.2 | length 882.5
  Top Layer w10: PLL1.2 3525.79,2234.21 3535,2225 3535,1605 3615,1525 J2.4
NetJ2_5: J2.5 PLL1.1 | length 849.2
  Top Layer w10: PLL1.1 3506.1,2228.9 3515,2220 J2.5
NetJ2_6: J2.6 PLL1.30 | length 1260.9
  Top Layer w10: J2.6 3409.07,1439.07 3336.79,1439.07 3330.93,1444.93 3330.93,1671.1 3470,1810.17 3470,2060 3330.93,2199.07 3330.93,2349.61 3336.79,2355.47 PLL1.30
NetOSC1_1: OSC1.1 R1.2 | length 288.1
  Top Layer w30: R1.2@1876.44,2250 1955,2250 1955,2340.04 1937.5,2357.54 1937.5,2392.47 1919.93,2410.04 OSC1.1
NetPLL1_5: PLL1.5 R5.2 R12.1 | length 485.3
  Top Layer w10: PLL1.5 3584.84,2140.16 3640,2085 R12.1 3641.67,2065 3680,2065 3705,2040 3795,2040 3813.33,2021.67 R5.2
NetPLL1_22: PLL1.22 R4.1 | length 161.1
  Top Layer w10: PLL1.22 3545.47,2575.47 3570,2600 R4.1
NetPLL1_25: PLL1.25 R8.1 | length 262.8
  Top Layer w10: R8.1 3386.54,2483.46 3416.1,2453.9 PLL1.25
NetR10_1: R10.1 R11.2 | length 78.7
  Top Layer w10: R10.1 3725,1920 3750,1945 R11.2
NetR11_1: R11.1 R12.2 | length 122.8
  Top Layer w10: R12.2 3670,2035 3700,2005 3749.17,2005 R11.1
pads on no net: PLL1.14 PLL1.15

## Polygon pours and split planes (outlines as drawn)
GND on Bottom Layer "bottom" (solid, pour order 2): 1000,1000 7000,1000 7000,5000 1000,5000
GND on GND "gn" (solid, pour order 3): 1000,1000 7000,1000 7000,5000 1000,5000
GND on Power "power" (solid, pour order 1): 1000,1000 7000,1000 7000,5000 1000,5000
GND on Top Layer "GND_L01_P004" (solid, pour order 4): 1000,1000 7000,1000 7000,5000 1000,5000

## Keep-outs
Keep-Out Layer:
  the board outline again, w8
